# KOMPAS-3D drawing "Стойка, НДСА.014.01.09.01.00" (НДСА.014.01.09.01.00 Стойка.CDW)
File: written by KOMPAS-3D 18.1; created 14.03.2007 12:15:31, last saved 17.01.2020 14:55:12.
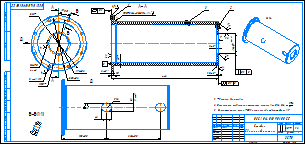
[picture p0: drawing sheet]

Sheet 1: A4x3, landscape

Document properties: Автор: Ширяева О.А.; Организация: Эсто-вакуум; Форматы листов документа: A4@4~3; Полное имя файла: НДСА.014.01.09.01.00 Стойка.a3d; PDM_DOCXDTO: <item xmlns="http://appius.ru/pdm" xmlns:xs="http://www.w3.org/2001/XMLSchema" xmlns:xsi="http://www.w3.org/2001/XMLSchema-instance" xsi:type="item">  <element xmlns:d2p1="http://v8.1c.ru/8.1/data/enterprise/current-config" xsi:type="d2p1:CatalogRef.aps_Элемен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; Масса: 20.7869

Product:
- Part/product: Стойка  | designation НДСА.014.01.09.01.00
    Масса: 20.7869
  - Component [detail]: Шов сварной 1 (стойка)  | qty 2  | Материал: Сталь 20  ГОСТ 1050-88 (density 7820 kg/m3); Масса: 0.0542527; source file: Шов сварной 1 (стойка).m3d
  - Component [detail]: Фланец верхний  | designation НДСА.014.01.09.01.03  | Материал: Сталь 20  ГОСТ 1050-88 (density 7820 kg/m3); Масса: 1.2704; source file: НДСА.014.01.09.01.03 Фланец верхний.m3d
  - Component [detail]: Труба  | designation НДСА.014.01.09.01.02  | Материал: Труба$d180х10 ГОСТ 8732-78;20 ГОСТ 8731-74$ (density 7859 kg/m3); Масса: 17.4852; source file: НДСА.014.01.09.01.02 Труба.m3d
  - Component [detail]: Фланец нижний  | designation НДСА.014.01.09.01.01  | Материал: Сталь 20 ГОСТ 1050-88 (density 7859 kg/m3); Масса: 1.92271; source file: НДСА.014.01.09.01.01 Фланец нижний.m3d

Title block, sheet 1: Наименование: Стойка / Сборочный чертеж; Масса: 20,79; scale: 1:2; Количество листов документа: 1; organisation: ЭСТО; Форматы листов документа: A4 3; stored path: D:\Шлейф\УКРД.762.10.00.00.00 Верхняя стойка\УКРД.762.10.01.00.00 СБ Стойка.cdw; Разработал: Волкова; Разработал, date: 17.01.2020

Views: Разрез А-А, Разрез Б-Б, Вид 5, Вид по стрелке 6
Referenced files in E:\НДСА.014.01.09.00.00 Верхняя стойка гидроподъемника\: Шов сварной 1 (стойка).m3d, НДСА.014.01.09.01.03 Фланец верхний.m3d, НДСА.014.01.09.01.02 Труба.m3d, НДСА.014.01.09.01.01 Фланец нижний.m3d, НДСА.014.01.09.01.00 Стойка.a3d
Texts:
  ГОСТ 5264-80-С11- 6,3
  НДСА.014.01.09.01.00
  Фланец нижний
  НДСА.014.01.09.01.01
  Труба
  НДСА.014.01.09.01.02
  Шов сварной 1 (стойка)
  Фланец верхний
  НДСА.014.01.09.01.03
Dimensions and other numbers on the sheet: 10; 446; 3,2; 0,1; 84; 1; 2; 6,3; 1,5; 3; 1,6; 185±0,5; 225±0,5; 42; 32; 2 отв.; 16; 1:2; 20,79; 17.01.2020

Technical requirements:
  * Размеры для справок.
  Неуказанные предельные отклонения размеров по H14, h14,    IT14 2 .
  Покрытие эмаль серая, 7001, кроме резьб. отверстий и пов. Г.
